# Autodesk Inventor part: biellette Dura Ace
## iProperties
Created: 2011-11
Part Number: biellette Dura Ace
Document SubType Name: Modeling
Designer: Laur
Density: 1 g/cm^3
Mass: 0.948014 g
Surface Area: 10.6455 cm^2
Volume: 0.948014 cm^3
Author: Laur
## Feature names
1. Extrusion1
